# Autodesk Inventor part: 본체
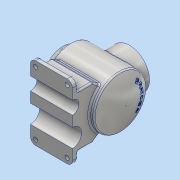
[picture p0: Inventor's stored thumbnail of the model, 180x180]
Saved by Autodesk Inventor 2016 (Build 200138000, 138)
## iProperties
Created: 2018-08
Part Number: 본체
Material: 알루미늄 6061
Document SubType Name: Modeling
Designer: 605-11
Density: 2.7 g/cm^3
Appearance: 알루미늄 - 평지
Mass: 1879.14 g
Surface Area: 1087.37 cm^2
Volume: 695.98 cm^3
Author: 605-11
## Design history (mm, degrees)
sketch "스케치1"
  geometry: L1 (0, 0)-(69.299, 0); L2 (0, 0)-(12, 0); L3 (12, 0)-(12, 38); L4 (12, 38)-(0, 38); L5 (0, 38)-(0, 0); L6 (12, 0)-(120, 0); L7 (108.671, 50)-(12, 50); L8 (12, 50)-(12, 0); A1 r 116 centre (4, 0) between (120, 0) and (108.671, 50)
  constraints: 16 end point, 3 horizontal, 3 parallel, 2 point on circle, 1 centre point, 1 horizontal alignment, 1 perpendicular, 1 point on line
  dimensions: "d0" = 76 diameter of L4 L1; "d1" = 100 diameter of L7 L1; "d2" = 12 distance of L3.end L4.end; "d5" = 232 diameter of A1; "d6" = 108 distance of L2.end L6.end; "d8" = 50 distance of L7.end L2.end
revolve "회전1" sketch "스케치1" stored, may be unused: angle "d9" = 90 deg
node "작업 평면1"
sketch "스케치3"
  geometry: L1 (-20, -70)-(-100, -70); L2 (-100, -70)-(-100, 70); L3 (-100, 70)-(-20, 70); L4 (-20, 70)-(-20, -70); 2 further points
  constraints: 8 end point, 2 parallel, 1 horizontal, 1 horizontal alignment, 1 midpoint, 1 perpendicular
  dimensions: "d17" = 140 distance of L1.end L2.end; "d18" = 80 distance of L1.start L1.end; "d20" = 20 horizontal distance of L1.start point (0, 0)
extrude "돌출1" join sketch "스케치3" distance "d21" = 10; taper "d22" = 0 deg
node "작업 평면2"
sketch "스케치4"
  geometry: C1 r 38 at (-62, 0); 1 further point
  constraints: 1 centre point, 1 horizontal alignment
  dimensions: "d24" = 76 diameter of C1; "d25" = 62 distance of C1.centre point (0, 0)
extrude "돌출2" join sketch "스케치4" stored distance "d26" = 10; taper "d27" = 0 deg
sketch "스케치5"
  geometry: L1 (0, 10)-(140, 10) reference; L2 (0, 0)-(0, 10) reference; L3 (140, 0)-(140, 10) reference; L4 (20, 0)-(120, 0); L5 (120, 0)-(120, 38.563); L6 (89.585, 82)-(50.415, 82); L7 (20, 38.563)-(20, 0); L8 (140, 0)-(0, 0) reference; L9 (120, 38.563)-(89.585, 82); L10 (20, 38.563)-(50.479, 82.091); 1 further point
  constraints: 12 end point, 2 parallel, 1 collinear, 1 horizontal, 1 perpendicular, 1 point on line
  dimensions: "d30" = 20 distance between parallel lines of L5 L3; "d31" = 20 distance between parallel lines of L7 L2; "d36" = 35 deg angle of L3 L9; "d37" = 82 distance from line of L6.start L4; "d38" = 35 deg angle of L10 L2; "d39" = 43.43704 vertical distance of L5.end L6.start; "d41" = 82.09079 distance from line of L10.end L4; "d42" = 43.52783 vertical distance of L7.start L10.end
extrude "돌출3" join sketch "스케치5" distance "d33" = 80; taper "d34" = 0 deg
sketch "스케치7"
  geometry: L1 (-140, 0)-(0, 0) reference; L2 (0, 0)-(-140, 0) reference; C1 r 12.5 at (-97.5, 0); C2 r 17.5 at (-47.5, 0); C3 r 50 at (-70, 82) reference; 1 further point
  constraints: 2 centre point, 2 horizontal alignment, 2 point on line
  dimensions: "d43" = 22.5 horizontal distance of C2.centre point (-70, 82); "d44" = 27.5 horizontal distance of point (-70, 82) C1.centre; "d45" = 35 diameter of C2; "d46" = 25 diameter of C1
extrude "돌출4" cut sketch "스케치7" stored distance "d47" = 80; taper "d48" = 0 deg
sketch "스케치2"
  geometry: L1 (0, 0)-(106.094, 0); L2 (0, 0)-(22, 0); L3 (22, 0)-(22, 27); L4 (22, 27)-(0, 27); L5 (0, 27)-(0, 0); L6 (22, 0)-(110, 0); L7 (102.163, 40)-(22, 40); L8 (22, 40)-(22, 0); A1 r 116 centre (4, 0) between (108.671, -50) and (108.671, 50) reference; A2 r 106 centre (4, 0) between (110, 0) and (102.163, 40)
  constraints: 16 end point, 3 horizontal, 3 parallel, 2 point on circle, 1 centre point, 1 perpendicular
  dimensions: "d10" = 10 radial gap between concentric circles of A2 A1; "d11" = 54 diameter of L4 L1; "d12" = 80 diameter of L7 L1; "d13" = 22 distance of L3.end L4.end; "d14" = 40 distance of L7.end L2.end
revolve "회전2" sketch "스케치2" stored, may be unused: angle "d15" = 90 deg
fillet "모깎기1" dims "d49" = 10
sketch "스케치9"
  geometry: A1 r 10 centre (30, -60) between (20, -60) and (30, -70) reference; A2 r 10 centre (90, -60) between (90, -70) and (100, -60) reference; A3 r 10 centre (90, 60) between (100, 60) and (90, 70) reference; A4 r 10 centre (30, 60) between (30, 70) and (20, 60) reference; 5 further points
  constraints: 4 coincident
hole "구멍1" sketch "스케치9" at (30, -60), (90, -60), (30, 60), (90, 60) diameter "d50" = 8; stored, may be unused: countersink angle "d54" = 90 deg, drill point angle "d56" = 0 deg; dims "d51" = 6, "d52" = 4, "d53" = 2, "d55" = 8
sketch "스케치10"
  geometry: C1 r 38 at (0, 0) reference; C2 r 27 at (0, 0); 1 further point
  constraints: 1 centre point
  dimensions: "d57" = 54 diameter of C2
extrude "돌출5" cut sketch "스케치10" distance "d58" = 80; taper "d59" = 0 deg
sketch "스케치11"
  geometry: L1 (-50, -50)-(-50, 50) reference; C1 r 27 at (0, 0) reference; 2 further points
  constraints: 1 horizontal alignment
  dimensions: "d62" = 32.5 distance of point (32.5, 0) C1.centre
hole "구멍2" sketch "스케치11" at (32.5, 0) diameter "d63" = 3.242; stored, may be unused: countersink angle "d67" = 90 deg, drill point angle "d69" = 118 deg; dims "d64" = 8, "d65" = 4, "d66" = 2, "d68" = 10
sketch "스케치12"
  geometry: 2 further points
  constraints: 1 vertical alignment
  dimensions: "d73" = 32.5 distance of point (0, 32.5) point (0, 0)
hole "구멍3" sketch "스케치12" at (0, 32.5) diameter "d74" = 3.242; stored, may be unused: countersink angle "d78" = 90 deg, drill point angle "d80" = 118 deg; dims "d75" = 8, "d76" = 4, "d77" = 2, "d79" = 10
fillet "모깎기2" dims "d84" = 3
fillet "모깎기3" dims "d85" = 3
fillet "모깎기4" dims "d86" = 3
fillet "모깎기5" dims "d87" = 3
chamfer "모따기1" distance "d88" = 1; stored, may be unused: second distance "d89" = 2, angle "d90" = 45 deg
fillet "모깎기6" dims "d91" = 3
chamfer "모따기2" distance "d92" = 1; stored, may be unused: second distance "d93" = 2, angle "d94" = 45 deg
fillet "모깎기7" dims "d95" = 3
fillet "모깎기8" dims "d96" = 3
fillet "모깎기9" dims "d97" = 3
node "작업 평면3"
sketch "스케치13"
  geometry: 1 further point
sketch "스케치14"
  geometry: C1 r 32.5 at (0, 0); 1 further point
  constraints: 1 centre point, 1 coincident, 1 other
  dimensions: "d98" = 65 diameter of C1
feature "엠보싱1" sketch "스케치14" dims "d10" = 10, "d11" = 54, "d12" = 80, "d13" = 22, "d14" = 40, "d99" = 0.5, "d100" = 0
node "솔리드1"
pattern_circular "원형 패턴1" dims angle "d71" = 360 deg
pattern_circular "원형 패턴2" dims angle "d82" = 360 deg
other parameters: "d16" = -82, "d23" = 147
